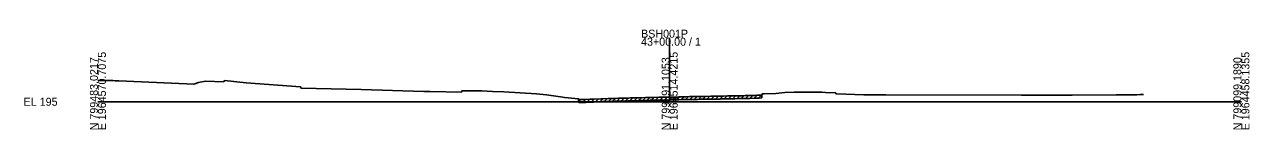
# Model space of a CAD drawing. Extents: x -26 to 1403, y -10 to 19587.
# Drawn here: x 974.3 to 1402.8, y 6990.3 to 7025.3 of the extents above; entities that cross this region are included whole.
import ezdxf

# ---------------------------------------------------------------- set-up
doc = ezdxf.new("R2010")
doc.units = 0
for name, color, linetype in [('Default', 7, 'Continuous'), ('RD_GPK_XS_Cell', 7, 'Continuous'), ('RD_XS_ExGround', 7, 'Continuous'), ('RD_XS_ExPaveRet', 7, 'Continuous'), ('RD_XS_TX_Elev_EX', 7, 'Continuous')]:
    doc.layers.add(name, color=color, linetype=linetype)

msp = doc.modelspace()

# ---------------------------------------------------------------- linework, layer by layer
at = {"layer": 'RD_GPK_XS_Cell'}
for p, q in [((1200, 7000), (1200, 7022.44)), ((1000, 7000), (1200, 7000)), ((1200, 7000), (1400, 7000))]:
    msp.add_line(p, q, dxfattribs=at)
at = {"layer": 'RD_XS_ExGround'}
msp.add_lwpolyline([(1000, 7007.48), (1000.7, 7007.47), (1005.18, 7007.4), (1006.08, 7007.37), (1007.28, 7007.34), (1010.01, 7007.26), (1033.57, 7006.11), (1035.23, 7006.77), (1037.62, 7007.21), (1044, 7006.95), (1044.24, 7007.39), (1051.88, 7006.59), (1070.87, 7005.18), (1071.09, 7004.73), (1092.03, 7004.33), (1113.95, 7003.64), (1116.09, 7003.59), (1127.14, 7003.33), (1127.28, 7003.78), (1130.94, 7003.82), (1132.87, 7003.83), (1133.35, 7003.83), (1133.86, 7003.83), (1134.31, 7003.81), (1137.98, 7003.61), (1142.03, 7003.43), (1153.43, 7002.77), (1155.72, 7002.54), (1156.92, 7002.38), (1162.66, 7001.55), (1163.22, 7001.43), (1164.46, 7001.42), (1168.04, 7001.04), (1168.06, 7000.96), (1168.19, 7000.73), (1169.07, 7000.76), (1170.21, 7000.78), (1170.73, 7000.79), (1172.04, 7000.85), (1173.33, 7000.91), (1175.93, 7001.01), (1176.55, 7001.03), (1178.54, 7001.11), (1179.1, 7001.13), (1180.44, 7001.18), (1181.13, 7001.19), (1182.09, 7001.22), (1183.71, 7001.25), (1185.4, 7001.29), (1186.32, 7001.32), (1186.7, 7001.33), (1188.93, 7001.39), (1190.14, 7001.42), (1191.52, 7001.47), (1193.19, 7001.51), (1194.31, 7001.53), (1196.17, 7001.56), (1196.74, 7001.56), (1198.21, 7001.59), (1199.36, 7001.61), (1200.26, 7001.62), (1201.97, 7001.66), (1203.2, 7001.7), (1204.57, 7001.74), (1205.66, 7001.77), (1206.94, 7001.8), (1207.38, 7001.8), (1209.8, 7001.84), (1210.32, 7001.85), (1212.41, 7001.87), (1214.35, 7001.9), (1215.02, 7001.91), (1216.22, 7001.93), (1217.61, 7001.96), (1218.3, 7001.97), (1218.78, 7001.98), (1220.2, 7002.02), (1220.93, 7002.04), (1222.79, 7002.07), (1224.39, 7002.1), (1225.4, 7002.12), (1226.41, 7002.15), (1228.01, 7002.18), (1229.75, 7002.24), (1230.51, 7002.27), (1231.31, 7002.3), (1232.16, 7002.36), (1232.3, 7002.36), (1232.4, 7002.81), (1233.1, 7002.83), (1237.18, 7002.88), (1240.25, 7003.2), (1243.5, 7003.41), (1253.18, 7003.37), (1255.85, 7003.18), (1257.99, 7003.23), (1258.13, 7002.78), (1258.45, 7002.77), (1267.97, 7002.46), (1270.44, 7002.44), (1275.59, 7002.42), (1323.11, 7002.28), (1340.77, 7002.26), (1356.25, 7002.42), (1363.46, 7002.48), (1364.6, 7002.5), (1365.8, 7002.51)], dxfattribs=at)
at = {"layer": 'RD_XS_ExPaveRet'}
for p, q in [((1229.56, 7001.24), (1230.6, 7002.27)), ((1231.06, 7001.29), (1232.12, 7002.35)), ((1232.3, 7002.36), (1232.3, 7001.36)), ((1168.06, 6999.99), (1168.06, 7000.99)), ((1168.06, 6999.99), (1168.82, 7000.75)), ((1168.06, 6999.99), (1168.19, 6999.73)), ((1168.19, 6999.73), (1169.07, 6999.76)), ((1169.07, 6999.76), (1170.21, 6999.78)), ((1169.56, 6999.77), (1170.58, 7000.79)), ((1170.21, 6999.78), (1170.73, 6999.79)), ((1170.73, 6999.79), (1172.04, 6999.85)), ((1171.06, 6999.81), (1172.11, 7000.85)), ((1172.04, 6999.85), (1173.33, 6999.91)), ((1172.56, 6999.87), (1173.6, 7000.92)), ((1173.33, 6999.91), (1175.93, 7000.01)), ((1174.06, 6999.94), (1175.1, 7000.98)), ((1175.56, 7000), (1176.6, 7001.04)), ((1175.93, 7000.01), (1176.55, 7000.03)), ((1176.55, 7000.03), (1178.54, 7000.11)), ((1177.06, 7000.05), (1178.1, 7001.09)), ((1178.54, 7000.11), (1179.1, 7000.13)), ((1178.56, 7000.11), (1179.6, 7001.15)), ((1179.1, 7000.13), (1180.44, 7000.18)), ((1180.06, 7000.17), (1181.08, 7001.19)), ((1180.44, 7000.18), (1181.13, 7000.19)), ((1181.13, 7000.19), (1182.09, 7000.22)), ((1181.56, 7000.21), (1182.58, 7001.23)), ((1182.09, 7000.22), (1183.71, 7000.25)), ((1183.06, 7000.24), (1184.08, 7001.26)), ((1183.71, 7000.25), (1185.4, 7000.29)), ((1184.56, 7000.27), (1185.59, 7001.3)), ((1185.4, 7000.29), (1186.32, 7000.32)), ((1186.06, 7000.31), (1187.09, 7001.34)), ((1186.32, 7000.32), (1186.7, 7000.33)), ((1186.7, 7000.33), (1188.93, 7000.39)), ((1187.56, 7000.35), (1188.59, 7001.38)), ((1188.93, 7000.39), (1190.14, 7000.42)), ((1189.06, 7000.39), (1190.09, 7001.42)), ((1190.14, 7000.42), (1191.52, 7000.47)), ((1190.56, 7000.44), (1191.59, 7001.47)), ((1191.52, 7000.47), (1193.19, 7000.51)), ((1192.06, 7000.48), (1193.09, 7001.51)), ((1193.19, 7000.51), (1194.31, 7000.53)), ((1193.56, 7000.52), (1194.58, 7001.54)), ((1194.31, 7000.53), (1196.17, 7000.56)), ((1195.06, 7000.54), (1196.07, 7001.55)), ((1196.17, 7000.56), (1196.74, 7000.56)), ((1196.56, 7000.56), (1197.57, 7001.58)), ((1196.74, 7000.56), (1198.21, 7000.59)), ((1198.06, 7000.58), (1199.08, 7001.6)), ((1198.21, 7000.59), (1199.36, 7000.61)), ((1199.36, 7000.61), (1200.26, 7000.62)), ((1199.56, 7000.61), (1200.58, 7001.63)), ((1200.26, 7000.62), (1201.97, 7000.66)), ((1201.06, 7000.64), (1202.08, 7001.67)), ((1201.97, 7000.66), (1203.2, 7000.7)), ((1202.56, 7000.68), (1203.59, 7001.71)), ((1203.2, 7000.7), (1204.57, 7000.74)), ((1204.06, 7000.73), (1205.09, 7001.75)), ((1204.57, 7000.74), (1205.66, 7000.77)), ((1205.56, 7000.76), (1206.58, 7001.79)), ((1205.66, 7000.77), (1206.94, 7000.8)), ((1206.94, 7000.8), (1207.38, 7000.8)), ((1207.06, 7000.8), (1208.08, 7001.81)), ((1207.38, 7000.8), (1209.8, 7000.84)), ((1208.56, 7000.82), (1209.58, 7001.84)), ((1209.8, 7000.84), (1210.32, 7000.85)), ((1210.06, 7000.84), (1211.07, 7001.86)), ((1210.32, 7000.85), (1212.41, 7000.87)), ((1211.56, 7000.86), (1212.57, 7001.87)), ((1212.41, 7000.87), (1214.35, 7000.9)), ((1213.06, 7000.88), (1214.07, 7001.9)), ((1214.35, 7000.9), (1215.02, 7000.91)), ((1214.56, 7000.9), (1215.58, 7001.92)), ((1215.02, 7000.91), (1216.22, 7000.93)), ((1216.06, 7000.93), (1217.08, 7001.95)), ((1216.22, 7000.93), (1217.61, 7000.96)), ((1217.56, 7000.96), (1218.58, 7001.98)), ((1217.61, 7000.96), (1218.3, 7000.97)), ((1218.3, 7000.97), (1218.78, 7000.98)), ((1218.78, 7000.98), (1220.2, 7001.02)), ((1219.06, 7000.99), (1220.09, 7002.02)), ((1220.2, 7001.02), (1220.93, 7001.04)), ((1220.56, 7001.03), (1221.58, 7002.05)), ((1220.93, 7001.04), (1222.79, 7001.07)), ((1222.06, 7001.06), (1223.08, 7002.07)), ((1222.79, 7001.07), (1224.39, 7001.1)), ((1223.56, 7001.09), (1224.58, 7002.11)), ((1224.39, 7001.1), (1225.4, 7001.12)), ((1225.06, 7001.12), (1226.08, 7002.14)), ((1225.4, 7001.12), (1226.41, 7001.15)), ((1226.41, 7001.15), (1228.01, 7001.18)), ((1226.56, 7001.15), (1227.58, 7002.17)), ((1228.01, 7001.18), (1229.75, 7001.24)), ((1228.06, 7001.19), (1229.09, 7002.22)), ((1229.75, 7001.24), (1230.51, 7001.27)), ((1230.51, 7001.27), (1231.31, 7001.3)), ((1231.31, 7001.3), (1232.16, 7001.36)), ((1232.16, 7001.36), (1232.3, 7001.36))]:
    msp.add_line(p, q, dxfattribs=at)

# ---------------------------------------------------------------- texts
at = {"layer": 'Default'}
msp.add_text('-', height=0.0001, dxfattribs=at).set_placement((1000, 7000))
at = {"layer": 'RD_GPK_XS_Cell'}
for s, p in [('BSH001P', (1190, 7022.44)), ('43+00.00 / 1', (1190, 7019.64)), ('EL 195', (974, 6998.6))]:
    msp.add_text(s, height=2.8, dxfattribs=at).set_placement(p)
for s, p in [('N 799483.0217', (1000, 6990)), ('E 1964570.7075', (1002.8, 6990)), ('N 799291.1053', (1200, 6990)), ('E 1964514.4215', (1202.8, 6990)), ('N 799099.1890', (1400, 6990)), ('E 1964458.1355', (1402.8, 6990))]:
    msp.add_text(s, height=2.8, rotation=90, dxfattribs=at).set_placement(p)
at = {"layer": 'RD_XS_TX_Elev_EX'}
msp.add_text('196.62', height=1, dxfattribs=at).set_placement((1197.96, 6999.12))

doc.saveas('drawing.dxf')
